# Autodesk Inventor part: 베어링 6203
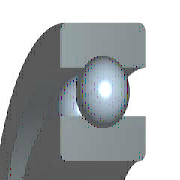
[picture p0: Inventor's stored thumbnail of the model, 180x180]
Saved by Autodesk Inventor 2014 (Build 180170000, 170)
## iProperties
IsCustomPart: 0
Created: 2014-10
Part Number: 베어링 6203
Material: 강철, 연강
Description: 깊은 그루브 볼 베어링
Document SubType Name: Modeling
Standard: KS B 2023
Designer: KYOUNG IL JANG
Standards Organization: KS
Language: ko-KR
Size Designation: 6203 - 17 x 40 x 12
Categories: <MemberInstance><Categories><Category DisplayName="샤프트 부품" InternalName="7f7aeb1f-a693-4053-b835-cee3144e0d98" Mnemonic="SHFT"><Category DisplayName="베어링" Inter
Density: 7.86 g/cm^3
Mass: 64.9809 g
Surface Area: 64.3582 cm^2
Volume: 8.26729 cm^3
Appearance: 노란색
Author: SeoGD™ [www.esajin.kr]
Revision Number: 1
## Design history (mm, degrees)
sketch "스케치" dims "d0" = 5.98 (= -0.26 x WD + 0.26 x BD)
  geometry: L1 (3.01, 14.25)-(8.99, 14.25); L2 (6, 14.25)-(6, 11.26); L3 (6, 14.25)-(6, 17.24); L4 (3.778, 12.249)-(0, 12.249); L5 (0, 8.5)-(12, 8.5); L6 (3.778, 16.251)-(0, 16.251); L7 (0, 20)-(12, 20); L8 (12, 8.5)-(12, 12.249); L9 (8.222, 12.249)-(12, 12.249); L10 (8.222, 16.251)-(12, 16.251); L11 (12, 20)-(12, 16.251); L12 (-1.4, 0)-(8.4, 0) reference; L13 (0, -0.3)-(0, 5.3) reference
  constraints: 22 end point, 4 point on line, 2 collinear, 2 perpendicular, 2 symmetric about line, 1 midpoint, 1 parallel, 14 other
  dimensions: "d9" = 17 diameter of L5 L12 (= WD); "d11" = 40 diameter of L7 L12 (= BD); "d12" = 12 distance between parallel lines of L8 L13 (= KB); "d13" = 24.498 diameter of L9 L12 (= 0.326 x BD + 0.674 x WD)
revolve "본체" stored, may be unused: angle "d6" = 90 deg
revolve "볼" stored, may be unused: angle "d7" = 90 deg
pattern_circular "IDS_ARRAYBALL[SIMPL:T]" dims angle "d3" = 360 deg
body "Solid1"
fillet "모깎기1" dims "d1" = 0.6 (= KRS)
other parameters: "WD" = 17 [user parameter; used in 5 equation terms], "BD" = 40 [user parameter; used in 5 equation terms], "KB" = 12 [user parameter; used in 1 equation term], "KRS" = 0.6 [user parameter; used in 1 equation term], "d4" = 0, "d5" = 0, "d8" = 0, "d14" = 0, "d15" = 0, "BBA" = 0 [user parameter], "BC0" = 4750000 [user parameter], "BC" = 9560000 [user parameter], "WR" = 8.5 (= 0.5 x WD) [user parameter]
